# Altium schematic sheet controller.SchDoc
size A
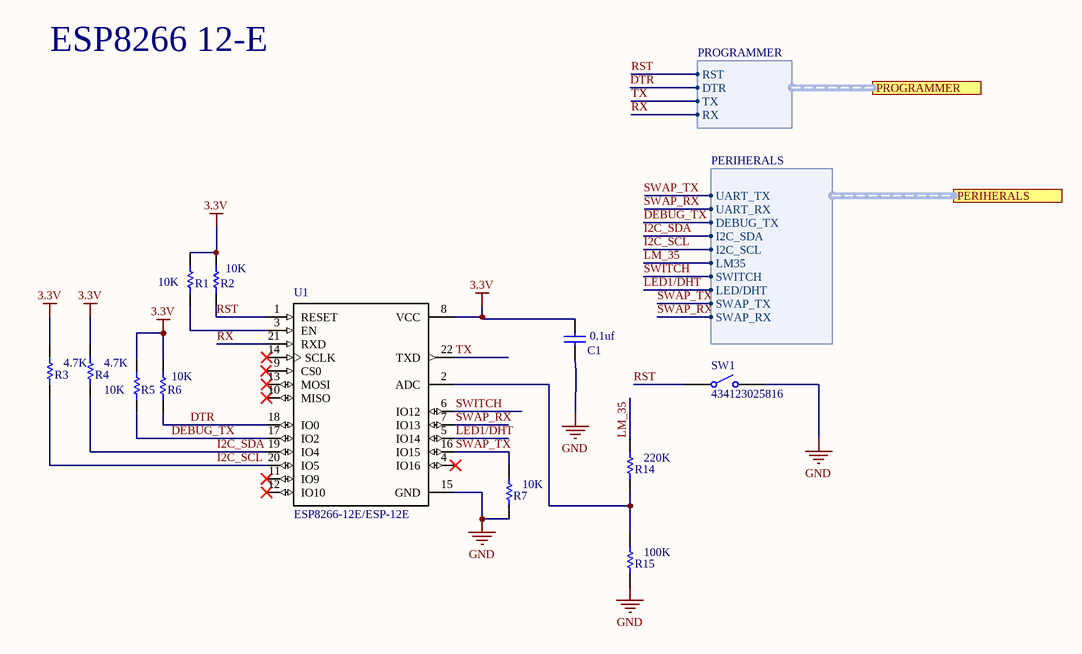
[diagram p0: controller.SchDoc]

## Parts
C1  0.1uf  [CAPC0603]
R1  10K  [RESC0603]
R2  10K  [RESC0603]
R3  4.7K  [RESC0603]
R4  4.7K  [RESC0603]
R5  10K  [RESC0603]
R6  10K  [RESC0603]
R7  10K  [RESC0603]
R14  220K  [RESC0603]
R15  100K  [RESC0603]
SW1  434123025816  [434123025816]
U1  ESP8266-12E/ESP-12E  [*XCVR_ESP8266-12E/ESP-12E]

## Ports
PERIHERALS (harness PERIHERALS), PROGRAMMER (harness PROGRAMMER)

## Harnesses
PROGRAMMER: RST, DTR, TX, RX
PERIHERALS: UART_TX, UART_RX, DEBUG_TX, I2C_SDA, I2C_SCL, LM35, SWITCH, LED/DHT, SWAP_TX, SWAP_RX

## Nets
3.3V: C1.1 R1.2 R2.2 R3.2 R4.2 R5.2 R6.2 U1.8(VCC)
GND: C1.2 R7.1 R15.1 SW1.2 U1.15(GND)
DEBUG_TX: R5.1 U1.17(IO2) ; port PERIHERALS.DEBUG_TX
DTR: R6.1 U1.18(IO0) ; port PROGRAMMER.DTR
I2C_SCL: R3.1 U1.20(IO5) ; port PERIHERALS.I2C_SCL
I2C_SDA: R4.1 U1.19(IO4) ; port PERIHERALS.I2C_SDA
LED1/DHT: U1.5(IO14) ; port PERIHERALS.LED/DHT
LM_35: R14.2 ; port PERIHERALS.LM35
RST: R2.1 SW1.1 U1.1(RESET) ; port PROGRAMMER.RST
RX: U1.21(RXD) ; port PROGRAMMER.RX
SWAP_RX: U1.7(IO13) ; port PERIHERALS.SWAP_RX
SWAP_TX: R7.2 U1.16(IO15) ; port PERIHERALS.SWAP_TX
SWITCH: U1.6(IO12) ; port PERIHERALS.SWITCH
TX: U1.22(TXD) ; port PROGRAMMER.TX
NetR1_1: R1.1 U1.3(EN)
NetR14_1: R14.1 R15.2 U1.2(ADC)

Not connected (* = marked no-connect by the designer): U1 4(IO16)* 9(CS0) 10(MISO)* 11(IO9)* 12(IO10)* 13(MOSI)* 14(SCLK)*

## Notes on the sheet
- ESP8266 12-E
- Labels drawn without touching a wire or pin: SWAP_RX, SWAP_TX

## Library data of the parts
C1 = CMP-2007-04765-1: Part Number: 08055C104KAJ2A; Manufacturer: AVX Interconnect / Elco
R1-R7 R14 R15 = CMP-1013-00215-1: 2R55 0.125W 1% 0805 (2012 Metric)  SMD; Case-Metric: 2012; Value: 2.55 Ohm; Case-EIA: 0805
SW1 = CMP-1460-00004-1: WS-TASV J-Bend SMD Tact Switch 6.0X3.8 mm; Manufacturer: Wuerth Elektronik; NoPins: 02
U1 = ESP8266-12E/ESP-12E: This WiFi module has a 32-bit MCU micro and clock speeds supporting 80 MHz or 160 MHz. Supports the RTOS and integrated Wi-Fi MAC/BB/RF/PA/LNA, and has an on-board antenna.; MF: AI-Thinker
